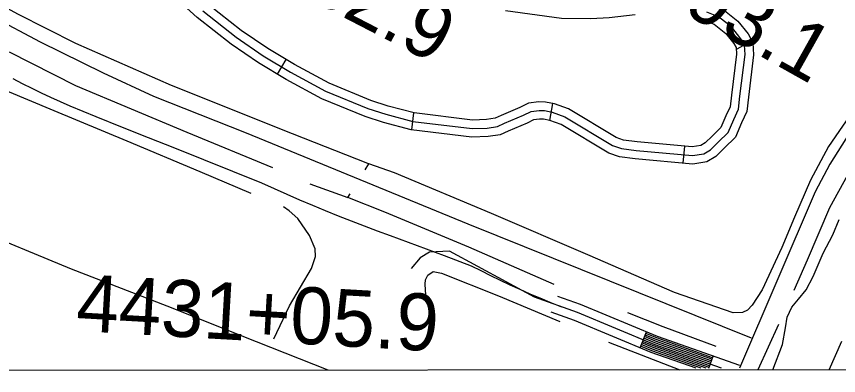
# Model space of a CAD drawing. Extents: x 3297753 to 3335611, y 652252 to 677623.
# Drawn here: x 3310374 to 3311817, y 657631 to 658261 of the extents above; entities that cross this region are included whole.
import ezdxf

# ---------------------------------------------------------------- set-up
doc = ezdxf.new("R2010")
doc.units = 0
for name, color, linetype in [('V-GRID-FRAM', 7, 'Continuous'), ('V-LEVE-TOET', 7, 'Continuous'), ('V-ROAD-CNTR', 7, 'Continuous'), ('V-SURV-IDEN', 7, 'Continuous'), ('V-SURV-LINE', 7, 'Continuous'), ('V-TOPO-SHOR', 7, 'Continuous')]:
    doc.layers.add(name, color=color, linetype=linetype)

msp = doc.modelspace()

# ---------------------------------------------------------------- linework, layer by layer
at = {"layer": 'V-GRID-FRAM'}
msp.add_lwpolyline([(3301859.6, 675814.9), (3333399.1, 675847), (3333425.5, 657662.7), (3301870.2, 657630.6), (3301859.6, 675814.9)], dxfattribs=at)
at = {"layer": 'V-LEVE-TOET'}
msp.add_lwpolyline([(3311701.2, 657640.6), (3311718.1, 657684.9), (3311723.5, 657714.4), (3311726.4, 657733.3), (3311734.9, 657750.7), (3311746.6, 657764.8), (3311759.8, 657781.2), (3311772, 657804.6), (3311789.9, 657845.5), (3311806.9, 657877.7), (3311817.5, 657904.6)], dxfattribs=at)
at = {"layer": 'V-ROAD-CNTR'}
for p, q in [((3311664.7, 658217.9), (3311638.4, 658203.5)), ((3310832, 658159.2), (3310847.4, 658184.9)), ((3311309.8, 658078.4), (3311315.3, 658107.9)), ((3311067.7, 658061.7), (3311071.4, 658091.5)), ((3311544.3, 658003.1), (3311547, 658033)), ((3311468.3, 657679.5), (3311479.8, 657707.2)), ((3311588.9, 657643.5), (3311596.4, 657664.7))]:
    msp.add_line(p, q, dxfattribs=at)
for points in [[(3313556.2, 659368.7), (3313244.3, 659132.5), (3312600.9, 658638.3), (3312100.3, 658280.8), (3312020.8, 658224.2), (3311951.6, 658174.5), (3311916.1, 658145.6), (3311885.3, 658114.7), (3311854.4, 658082.6), (3311829.3, 658046.2), (3311801.2, 658001.3), (3311775.9, 657953.2), (3311642.7, 657643.5)], [(3311329.7, 658071.2), (3311310, 658078.4), (3311299, 658080.4), (3311291.9, 658080.7), (3311281.6, 658079.4), (3311270.1, 658073.7), (3311236.7, 658059.5), (3311222.8, 658053), (3311201.6, 658049.9), (3311172.9, 658048.8), (3311066.5, 658061.8), (3311018, 658074.7), (3310985.8, 658085.2), (3310910, 658116.3), (3310847.4, 658150), (3310798.9, 658179.1), (3310750.8, 658212.1), (3310691.3, 658259), (3310630.6, 658314.5)], [(3311342.7, 658098.4), (3311318, 658107.4), (3311302.2, 658110.4), (3311290.6, 658110.7), (3311272.9, 658108.6), (3311257.5, 658100.9), (3311224.4, 658086.9), (3311214.1, 658082), (3311198.9, 658079.8), (3311174.1, 658078.9), (3311072.2, 658091.4), (3311026.5, 658103.5), (3310996.1, 658113.4), (3310922.8, 658143.4), (3310862.2, 658176.1), (3310815.1, 658204.4), (3310768.6, 658236.3), (3310710.7, 658281.9)], [(3310331.6, 658260.6), (3310415.7, 658215.9), (3310526, 658161.8), (3310614.6, 658120.6), (3310777.3, 658056.5), (3311166, 657896.9), (3311663.2, 657696.6)], [(3310701, 658270.4), (3310759.7, 658224.2), (3310807, 658191.7), (3310854.8, 658163), (3310916.4, 658129.8), (3310990.9, 658099.3), (3311022.2, 658089.1), (3311069.4, 658076.6), (3311173.5, 658063.8), (3311200.2, 658064.8), (3311218.4, 658067.5), (3311230.6, 658073.2), (3311263.8, 658087.3), (3311277.2, 658094), (3311291.2, 658095.7), (3311300.6, 658095.4), (3311314, 658092.9), (3311336.2, 658084.8), (3311420, 658034.5), (3311435.6, 658029.1), (3311461.6, 658025.6), (3311560.5, 658016.7), (3311580.3, 658019.9), (3311592.1, 658026.7), (3311605.3, 658040.3), (3311623, 658057.3), (3311632.7, 658080.1), (3311641, 658097.9), (3311643.6, 658120.9), (3311652.6, 658193.8), (3311651.7, 658210.4), (3311645.5, 658221.6), (3311629.2, 658241.6), (3311606.1, 658260), (3311585.5, 658268.1)], [(3311232.5, 658271), (3311330.7, 658257.4), (3311382.1, 658257.2), (3311414.4, 658258.9), (3311460, 658264)], [(3311613.7, 658273.2), (3311639.8, 658252.3), (3311658, 658230.1), (3311666.5, 658214.6), (3311667.6, 658193.2), (3311658.5, 658119.2), (3311655.6, 658093.8), (3311646.4, 658073.9), (3311635.6, 658048.6), (3311615.9, 658029.6), (3311601.4, 658014.8), (3311585.4, 658005.5), (3311561, 658001.6), (3311460, 658010.7), (3311432.1, 658014.5), (3311413.6, 658020.9), (3311329.7, 658071.2)], [(3311564.1, 658261.6), (3311579.5, 658254.3), (3311598.5, 658246.9), (3311618.6, 658230.8), (3311633, 658213.2), (3311636.9, 658206.2), (3311637.5, 658194.3), (3311628.7, 658122.7), (3311626.4, 658102), (3311619, 658086.2), (3311610.4, 658066), (3311594.7, 658050.9), (3311582.8, 658038.7), (3311575.2, 658034.3), (3311559.9, 658031.8), (3311463.3, 658040.6), (3311439.1, 658043.8), (3311426.3, 658048.2), (3311342.7, 658098.4)], [(3310368, 658151.6), (3310384.4, 658143.1), (3310400.9, 658134.8), (3310417.5, 658126.7), (3310434.1, 658118.9), (3310450.9, 658111.2), (3310467.8, 658103.7), (3310513.6, 658085), (3310559.4, 658066.5), (3310605.4, 658048.1), (3310651.4, 658029.9), (3310702.3, 658009.8), (3310753.1, 657989.3), (3310803.9, 657968.6), (3310826.1, 657958.6), (3310848.5, 657948.7), (3310870.9, 657939), (3310893.4, 657929.5), (3310916, 657920.1), (3310938.7, 657911), (3310961.4, 657902.1), (3310984.2, 657893.3), (3311007.1, 657884.8), (3311030.1, 657876.4), (3311077.4, 657858.9), (3311124.6, 657841.3), (3311171.8, 657823.4), (3311188.7, 657814.7), (3311205.8, 657806.2), (3311222.9, 657797.9), (3311240.1, 657789.8), (3311257.4, 657781.9), (3311274.8, 657774.2), (3311292.3, 657766.7), (3311309.8, 657759.3), (3311327.4, 657752.2), (3311330.4, 657751.1)], [(3311611.5, 657643.5), (3311493.3, 657685.3), (3311358.5, 657741.3), (3311283.2, 657768.2), (3311133.7, 657848.7), (3311098.6, 657847.3), (3311082.5, 657837.2), (3311066.8, 657818.4)], [(3311643.6, 657648), (3311498.7, 657699.3), (3311363.9, 657755.3), (3311323.9, 657769.6)], [(3311566.6, 657643.5), (3311487.9, 657671.3), (3311353.1, 657727.3), (3311312.4, 657741.8)], [(3311593.4, 657656.2), (3311495.4, 657690.9), (3311476.3, 657698.9)], [(3311594.4, 657659.1), (3311496.5, 657693.7), (3311477.5, 657701.7)], [(3311595.4, 657661.9), (3311497.6, 657696.5), (3311478.6, 657704.4)], [(3311584.5, 657643.5), (3311490.1, 657676.9), (3311470.6, 657685)], [(3311589.4, 657644.9), (3311491.1, 657679.7), (3311471.7, 657687.8)], [(3311590.4, 657647.8), (3311492.2, 657682.5), (3311472.9, 657690.6)], [(3311591.4, 657650.6), (3311493.3, 657685.3), (3311474, 657693.3)], [(3311592.4, 657653.4), (3311494.4, 657688.1), (3311475.2, 657696.1)], [(3311575.6, 657643.5), (3311489, 657674.1), (3311469.4, 657682.3)]]:
    msp.add_lwpolyline(points, dxfattribs=at)
at = {"layer": 'V-SURV-LINE'}
msp.add_lwpolyline([(3311800.3, 657640.7), (3311822.2, 657690.9)], dxfattribs=at)
at = {"layer": 'V-TOPO-SHOR'}
for p, q in [((3310986, 657991.8), (3310992.4, 658002.2)), ((3310888.9, 657967.2), (3310955.7, 657943.2))]:
    msp.add_line(p, q, dxfattribs=at)
for points in [[(3311848.3, 658104), (3311799.1, 658032.7), (3311767.3, 657973.6), (3311739.5, 657908.6), (3311717.3, 657855.5), (3311682.5, 657780.8), (3311665.2, 657753.9), (3311656.8, 657745.3), (3311647.9, 657741.3), (3311631.7, 657740.4), (3311529.1, 657776.2), (3311376.5, 657842.6), (3311207.9, 657914.9), (3311037.5, 657986), (3310992.4, 658002.2), (3310990.9, 658002.7), (3310858.4, 658054.9), (3310646.4, 658139.5), (3310478.5, 658213.3), (3310376.6, 658264.6), (3310287.6, 658314)], [(3310823.9, 657995), (3310673.8, 658056.9), (3310478.1, 658139), (3310361.6, 658198.1)], [(3310785.9, 657949.8), (3310696.4, 657988.2), (3310568.4, 658042.1), (3310440.4, 658094.8), (3310315, 658147.3)], [(3311738.8, 657780.3), (3311762.1, 657833.5), (3311801.2, 657925.6), (3311832.7, 657982.8), (3311858.7, 658020.2), (3311909.2, 658087), (3311921.3, 658099.7)], [(3311317.7, 657790.6), (3311167.8, 657855.9), (3311020.6, 657917.2), (3310955.7, 657943.2), (3310959.7, 657949.5)], [(3310826, 657695.1), (3310853.3, 657752.9), (3310892.1, 657818.2), (3310898.6, 657839.2), (3310898.2, 657852.8), (3310888.1, 657876.2), (3310867.6, 657906.2), (3310852.4, 657919.7), (3310842.4, 657926.6)], [(3310920.8, 657639.8), (3310795.4, 657689.7), (3310638.7, 657752.5), (3310470.7, 657817.3), (3310289.6, 657892.2)], [(3311092.3, 657771.8), (3311091.3, 657790.7), (3311091.8, 657798.6), (3311095.7, 657807), (3311105.4, 657813.3), (3311119.8, 657810), (3311219.9, 657770.4), (3311327.6, 657725.7)], [(3311601.7, 657681.4), (3311509, 657716), (3311446.7, 657740.5)], [(3311711.1, 657720.3), (3311675.1, 657640.6)], [(3311412.9, 657689), (3311538.4, 657640.4)]]:
    msp.add_lwpolyline(points, dxfattribs=at)

# ---------------------------------------------------------------- texts
at = {"layer": 'V-SURV-IDEN'}
for s, rotation, p in [('4429+32.9', 332.6436, (3310543.6, 658468.4)), ('4427+93.1', 330.7067, (3311213.4, 658452.4)), ('4431+05.9', 356.7356, (3310477.4, 657709))]:
    msp.add_text(s, height=100, rotation=rotation, dxfattribs=at).set_placement(p)

doc.saveas('drawing.dxf')
